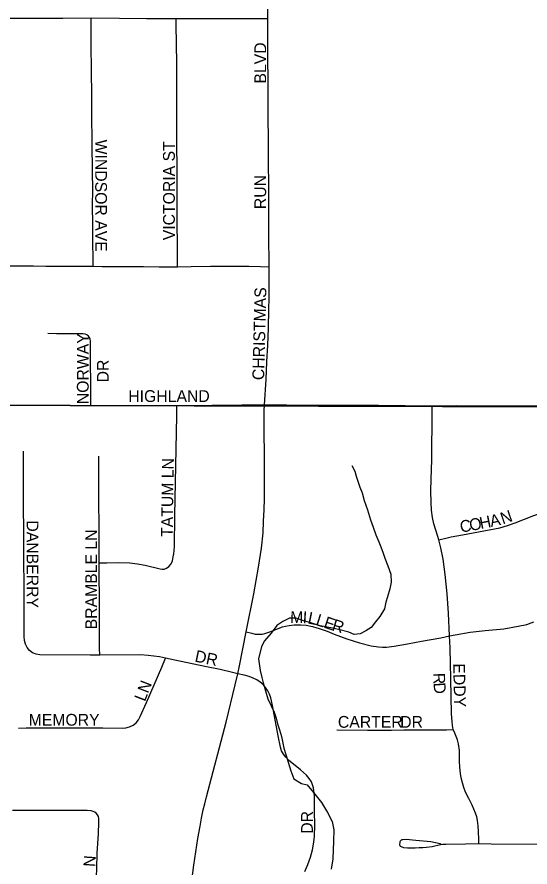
# Model space of a CAD drawing. Extents: x 1985906 to 2360102, y 891258 to 1222054.
# Drawn here: x 2121160 to 2123335, y 1028885 to 1032490 of the extents above; entities that cross this region are included whole.
import ezdxf

# ---------------------------------------------------------------- set-up
doc = ezdxf.new("R2010")
doc.units = 0
for name, color, linetype in [('GM_X_City_Street', 7, 'Continuous'), ('GM_X_City_Street_Text', 7, 'Continuous'), ('GM_X_Minor_River', 7, 'Continuous'), ('GM_X_Section', 7, 'Continuous')]:
    doc.layers.add(name, color=color, linetype=linetype)

msp = doc.modelspace()

# ---------------------------------------------------------------- linework, layer by layer
at = {"layer": 'GM_X_City_Street'}
for points in [[(2122223.4, 1032482.7), (2122223.8, 1032539.7), (2122224, 1032565.7), (2122224.2, 1032594.4), (2122224.7, 1032651.3)], [(2121115.7, 1032484.6), (2121222, 1032484.9), (2121299.3, 1032485.1), (2121354.8, 1032485.2), (2121474.6, 1032485.5)], [(2121474.6, 1032485.5), (2121595.4, 1032484.5), (2121710, 1032483.7), (2121824.3, 1032482.8), (2121835.6, 1032482.8)], [(2121483.5, 1031432.5), (2121483, 1031469.8), (2121482.2, 1031529.6), (2121481.8, 1031559.1), (2121481.4, 1031609.5), (2121481.2, 1031632.7), (2121481.1, 1031667.7), (2121481.1, 1031698.2), (2121481.6, 1031747.4), (2121479.3, 1031943.8), (2121478.1, 1032090.9), (2121476.9, 1032190.4), (2121476.4, 1032228.6), (2121475.6, 1032287.2), (2121475.1, 1032346.7), (2121474.6, 1032401.2), (2121474.6, 1032457.8), (2121474.6, 1032485.5)], [(2121835.6, 1032482.8), (2121978.3, 1032483.4), (2122069.6, 1032483.7), (2122152.8, 1032483.8), (2122184.1, 1032483.8), (2122223.4, 1032482.7)], [(2121840.3, 1031430.4), (2121840.2, 1031471.4), (2121839.9, 1031668.3), (2121839.4, 1031832.6), (2121838.4, 1031964), (2121837.3, 1032095.3), (2121837.5, 1032292.4), (2121835.8, 1032457.5), (2121835.6, 1032482.8)], [(2122228.9, 1031430.7), (2122228.8, 1031463), (2122228.6, 1031535.9), (2122228.5, 1031575), (2122228.5, 1031745.4), (2122227, 1031903.2), (2122226.6, 1031939.7), (2122226.2, 1031977), (2122225.4, 1032058.3), (2122224.8, 1032166.3), (2122224.6, 1032210.6), (2122223.9, 1032325.2), (2122223.4, 1032482.7)], [(2121110.2, 1031434.1), (2121133.3, 1031434.3), (2121166.7, 1031434.1), (2121230, 1031433.8), (2121282.1, 1031433.5), (2121369.8, 1031433.1), (2121483.5, 1031432.5)], [(2121483.5, 1031432.5), (2121521.8, 1031432.3), (2121569.5, 1031432), (2121627.7, 1031431.7), (2121696.3, 1031431.2), (2121763.2, 1031430.8), (2121840.3, 1031430.4)], [(2121840.3, 1031430.4), (2121898.9, 1031431.6), (2121980.5, 1031432.4), (2122094.7, 1031432.6), (2122143.5, 1031432.5), (2122192.2, 1031431.5), (2122228.9, 1031430.7)], [(2122209.7, 1030845.2), (2122216.7, 1030952.4), (2122220.2, 1031027.1), (2122223.6, 1031097.4), (2122226.3, 1031169.5), (2122228, 1031251.1), (2122228.9, 1031295.4), (2122229.8, 1031383.1), (2122228.9, 1031430.7)], [(2121473.9, 1030841.8), (2121473.7, 1030860.6), (2121473.4, 1030904.4), (2121473.2, 1030923.6), (2121472.9, 1030961.5), (2121472.6, 1030998.4), (2121472.4, 1031025.5), (2121472, 1031064.8), (2121471.7, 1031114.6), (2121470.1, 1031122.9), (2121468.7, 1031128.2), (2121466.5, 1031132.5), (2121463.5, 1031136.8), (2121456.1, 1031141.9), (2121449, 1031144.4), (2121440.1, 1031146), (2121393.1, 1031146.3), (2121363, 1031146.4), (2121327.1, 1031146.6), (2121290.7, 1031146.9)], [(2121093.7, 1030843.1), (2121181.9, 1030842.9), (2121473.9, 1030841.8)], [(2121473.9, 1030841.8), (2121542.9, 1030841.5), (2121838.2, 1030842.6)], [(2121509.3, 1030174.9), (2121540.7, 1030175.3), (2121589.7, 1030175.9), (2121638.7, 1030174.3), (2121671.2, 1030170.8), (2121703.4, 1030164.9), (2121766.9, 1030149.3), (2121775.3, 1030148.2), (2121784.8, 1030148.6), (2121793.9, 1030151.9), (2121804.6, 1030159.4), (2121813.5, 1030171.2), (2121819.5, 1030184.1), (2121822.8, 1030200.7), (2121825.1, 1030213.7), (2121826.6, 1030227.8), (2121827.7, 1030244), (2121830.1, 1030374.9), (2121837.5, 1030799.9), (2121838.2, 1030842.6)], [(2121838.2, 1030842.6), (2121986.1, 1030843.1), (2122018.7, 1030843.7)], [(2122018.7, 1030843.7), (2122113.1, 1030845.3), (2122209.7, 1030845.2)], [(2122132.1, 1029882.2), (2122164, 1030043.6), (2122184.8, 1030156.3), (2122196.7, 1030237.3), (2122203.3, 1030302.4), (2122205.9, 1030351.4), (2122208.5, 1030399.2), (2122209.1, 1030446.1), (2122209.6, 1030564.2), (2122209, 1030631.9), (2122208.2, 1030732.6), (2122208.8, 1030820.4), (2122209.7, 1030845.2)], [(2122209.7, 1030845.2), (2122303.4, 1030845.3), (2122482.3, 1030843.3), (2122692.5, 1030843.2), (2122920.7, 1030841.2)], [(2122948.6, 1030272.3), (2122945, 1030286.9), (2122927.2, 1030339.9), (2122921.4, 1030367), (2122917.3, 1030399), (2122916.3, 1030431.5), (2122914.8, 1030480.7), (2122916.5, 1030530.4), (2122918.7, 1030611.8), (2122918.6, 1030677.6), (2122920.5, 1030750), (2122920.5, 1030812.6), (2122920.7, 1030841.2)], [(2122920.7, 1030841.2), (2123021.8, 1030841.8), (2123250.6, 1030841.1), (2123413.4, 1030841), (2123599.9, 1030840.4), (2123847.1, 1030841)], [(2121510.9, 1029784.1), (2121470.6, 1029784.1), (2121257.6, 1029784.4), (2121241.5, 1029787), (2121226.4, 1029793.1), (2121213.3, 1029802.7), (2121202.9, 1029815.3), (2121195.7, 1029829.9), (2121191.7, 1029845.8), (2121190.2, 1029862.1), (2121190.5, 1030091.5), (2121189.2, 1030173.4), (2121189.4, 1030304.4), (2121187.8, 1030419.1), (2121188.2, 1030648.4)], [(2121509.3, 1030174.9), (2121509.1, 1030268.7), (2121507.9, 1030496.6), (2121507.3, 1030626.6)], [(2122948.6, 1030272.3), (2122984.7, 1030280.8), (2123000.7, 1030284.6), (2123049.1, 1030294), (2123162.3, 1030314.2), (2123207.1, 1030323.5), (2123239.8, 1030332.9), (2123273, 1030344.5), (2123351.3, 1030375.8), (2123419.2, 1030397.6), (2123515.9, 1030428.8), (2123570.5, 1030445.9), (2123611.9, 1030452.9), (2123669.6, 1030459.2), (2123723.4, 1030462.2), (2123774.9, 1030462.2), (2123831.8, 1030462.2), (2123859.4, 1030462.2)], [(2122994.3, 1029865), (2122990.3, 1029961.8), (2122984.5, 1030043.8), (2122976.2, 1030125.6), (2122966.6, 1030190.6), (2122956.9, 1030239), (2122948.6, 1030272.3)], [(2121510.9, 1029784.1), (2121510.8, 1029813.4), (2121509.8, 1029992.2), (2121509.3, 1030154.9), (2121509.3, 1030174.9)], [(2122132.1, 1029882.2), (2122155.3, 1029876.5), (2122170.3, 1029872.8), (2122179.4, 1029872), (2122186.6, 1029872), (2122200, 1029872.8), (2122211.5, 1029874.8), (2122235.9, 1029884.4), (2122267, 1029897), (2122286.2, 1029902.9), (2122298.4, 1029907), (2122314.6, 1029909.2), (2122335.8, 1029911.8), (2122363.9, 1029912.5), (2122386.1, 1029910.3), (2122412.7, 1029904.4), (2122441.6, 1029896.2), (2122474.9, 1029885.1), (2122504.5, 1029872.5), (2122559.2, 1029853.3), (2122611.8, 1029836.3), (2122661.2, 1029823.1), (2122693.6, 1029818.4), (2122710, 1029817.4), (2122726.3, 1029817.6), (2122758.9, 1029821.5), (2122815.2, 1029831), (2122875.2, 1029842.9), (2122957.3, 1029857.6), (2122994.3, 1029865)], [(2122994.3, 1029865), (2123017.3, 1029869.5), (2123081.6, 1029880.6), (2123145.3, 1029888.7), (2123223.7, 1029895.3), (2123285.1, 1029905.7), (2123322.1, 1029913.8), (2123339.9, 1029920.4), (2123351, 1029924.9)], [(2122096.1, 1029704.6), (2122103.6, 1029738.2), (2122132.1, 1029882.2)], [(2123009.9, 1029468.2), (2123008.2, 1029476.2), (2123006.4, 1029484.6), (2123005.4, 1029501.8), (2123002.7, 1029534.5), (2123000.1, 1029682.5), (2122996.1, 1029814), (2122994.3, 1029865)], [(2121166.4, 1029474.1), (2121199, 1029474.6), (2121361.7, 1029474.9), (2121524.4, 1029474.8), (2121605.8, 1029474.1), (2121622, 1029475.5), (2121637.8, 1029479.4), (2121652.5, 1029486.3), (2121665.3, 1029496.3), (2121675.4, 1029508.9), (2121683.2, 1029523.2), (2121708.8, 1029583), (2121773.7, 1029732.3), (2121790.4, 1029770.7)], [(2121790.4, 1029770.7), (2121764.9, 1029776.1), (2121716.2, 1029782.5), (2121683.5, 1029784.3), (2121510.9, 1029784.1)], [(2122096.1, 1029704.6), (2122073.7, 1029709.8), (2122021.2, 1029722), (2121957.1, 1029735.2), (2121829, 1029762.7), (2121790.4, 1029770.7)], [(2121880.6, 1028665.7), (2121884.4, 1028697.4), (2121909.6, 1028892.4), (2121926.6, 1029005.8), (2121936.4, 1029058.2), (2121942.5, 1029091.5), (2121950.3, 1029127.1), (2121956.4, 1029153.2), (2121963.9, 1029182.1), (2122046.5, 1029499.2), (2122085.8, 1029658.2), (2122096.1, 1029704.6)], [(2122380.4, 1028865.7), (2122393.9, 1028895.5), (2122404.9, 1028926.3), (2122413.1, 1028957.9), (2122418.2, 1028990.1), (2122421.2, 1029015.6), (2122423, 1029062.5), (2122422.2, 1029121.5), (2122421.8, 1029145), (2122421.3, 1029185.8), (2122417, 1029221.4), (2122412.6, 1029233.5), (2122408.3, 1029245.7), (2122398.7, 1029260.4), (2122387.1, 1029274.8), (2122362.3, 1029297.8), (2122310.7, 1029338.5), (2122299.8, 1029350.6), (2122290.1, 1029363.8), (2122282.3, 1029378.1), (2122277.3, 1029393.7), (2122267.9, 1029441.9), (2122243.8, 1029570.6), (2122236.1, 1029602.4), (2122230.7, 1029617.9), (2122223.5, 1029632.5), (2122214.4, 1029646.1), (2122203.5, 1029658.3), (2122191.2, 1029669.1), (2122177.8, 1029678.5), (2122161.5, 1029686.3), (2122145, 1029692.4), (2122123.1, 1029698.5), (2122096.1, 1029704.6)], [(2122517, 1029467.2), (2122645.7, 1029465.5), (2122747.5, 1029465.5), (2122800.1, 1029466.2), (2122834, 1029466.1), (2122899, 1029466.8), (2122941.2, 1029466.8), (2122981.1, 1029466.5), (2123009.9, 1029468.2)], [(2123118.4, 1028984.3), (2123118, 1029001.8), (2123116.5, 1029036.2), (2123114.8, 1029059.3), (2123112.5, 1029081.6), (2123109.3, 1029098.4), (2123104.5, 1029113.6), (2123090.1, 1029147.1), (2123076.6, 1029175.8), (2123062.2, 1029202.1), (2123054.3, 1029222.9), (2123048.7, 1029242), (2123043.9, 1029263.6), (2123040.7, 1029281.1), (2123037.5, 1029308.3), (2123036.7, 1029333.8), (2123035.9, 1029379.3), (2123032.8, 1029407.2), (2123028, 1029424), (2123022.4, 1029438.4), (2123016, 1029452.7), (2123009.9, 1029468.2)], [(2121492.6, 1028742.7), (2121498.5, 1028878.5), (2121500.6, 1028943.8), (2121505.2, 1029025.6), (2121507.4, 1029074.7), (2121507.2, 1029091.2), (2121505.3, 1029099.6), (2121501.7, 1029106.3), (2121496.5, 1029112.7), (2121490, 1029117.5), (2121483, 1029121.1), (2121474.9, 1029123.2), (2121458.5, 1029124.9), (2121141.7, 1029124.6)], [(2122958.2, 1028981.6), (2122954.3, 1028982.7), (2122915.3, 1028991.1), (2122851, 1028997.1), (2122810.8, 1029001.2), (2122796, 1029000.4), (2122791.5, 1028999.6), (2122789.1, 1028998.7), (2122786.6, 1028996.7), (2122785.2, 1028994.6), (2122783.9, 1028991.5), (2122782.8, 1028987.3), (2122782.4, 1028982.2), (2122782.5, 1028979.8), (2122783.3, 1028976.8), (2122785.5, 1028973.8), (2122788.4, 1028971.7), (2122799.3, 1028967.2), (2122815.9, 1028966.7), (2122848.8, 1028967), (2122865.2, 1028967.3), (2122881.2, 1028967.9), (2122896.7, 1028968.9), (2122920.4, 1028972.5), (2122955.1, 1028980.1), (2122965.3, 1028981.3), (2122978.4, 1028981.9), (2123062.1, 1028983.3), (2123118.4, 1028984.3)], [(2123118.4, 1028984.3), (2123170.9, 1028983.4), (2123378.5, 1028981.2)]]:
    msp.add_lwpolyline(points, dxfattribs=at)
at = {"layer": 'GM_X_Minor_River'}
msp.add_lwpolyline([(2122580, 1030587.7), (2122592.3, 1030563.7), (2122598.6, 1030541.8), (2122613.3, 1030495.8), (2122623.6, 1030471.9), (2122632.1, 1030439.9), (2122646.7, 1030400), (2122659.3, 1030358), (2122669.7, 1030326.1), (2122682.2, 1030294.2), (2122694.6, 1030264.2), (2122702.9, 1030242.3), (2122713.3, 1030216.4), (2122719.6, 1030194.4), (2122732.1, 1030162.5), (2122744.6, 1030126.5), (2122747, 1030092.5), (2122741.4, 1030064.3), (2122731.8, 1030030.1), (2122724, 1030007.9), (2122718.4, 1029979.8), (2122698.7, 1029947.4), (2122680.9, 1029925.1), (2122661.2, 1029900.8), (2122639.3, 1029886.4), (2122615.3, 1029874.1), (2122589.2, 1029871.7), (2122567, 1029881.5), (2122522.7, 1029892.9), (2122498.5, 1029898.6), (2122446.2, 1029907.9), (2122401.8, 1029921.4), (2122375.6, 1029929.1), (2122343.4, 1029940.7), (2122315.2, 1029940.3), (2122287.3, 1029925.9), (2122261.4, 1029909.5), (2122237.8, 1029877.1), (2122210.1, 1029844.6), (2122196.3, 1029820.4), (2122184.9, 1029768.1), (2122191.6, 1029718), (2122198, 1029688), (2122204.3, 1029666), (2122223.3, 1029598.1), (2122250.1, 1029542.3), (2122258.5, 1029516.3), (2122264.8, 1029492.3), (2122273.2, 1029466.4), (2122281.6, 1029438.4), (2122288, 1029410.4), (2122292.3, 1029388.4), (2122300.7, 1029362.5), (2122321.6, 1029292.5), (2122334.1, 1029258.6), (2122366.5, 1029239), (2122390.7, 1029233.3), (2122417.2, 1029201.5), (2122451.9, 1029157.9), (2122476.5, 1029116.1), (2122497.1, 1029078.3), (2122503.6, 1029042.2), (2122502.2, 1028994.1), (2122499.2, 1028919.8), (2122491.7, 1028875.6)], dxfattribs=at)
at = {"layer": 'GM_X_Section'}
for points in [[(2119771.9, 1036177.8), (2125019.2, 1036172.5), (2125066.6, 1030831.6), (2119807.2, 1030846.8)], [(2125066.6, 1030831.6), (2125102, 1025486.6), (2119810.6, 1025501.6), (2119807.2, 1030846.8)]]:
    msp.add_lwpolyline(points, close=True, dxfattribs=at)

# ---------------------------------------------------------------- texts
at = {"layer": 'GM_X_City_Street_Text'}
for s, rotation, p in [('BLVD', 90, (2122216.7, 1032207.3)), ('WINDSOR AVE', 270, (2121491.9, 1031969.7)), ('VICTORIA ST', 90, (2121829.5, 1031542.9)), ('RUN', 90, (2122216.7, 1031674.9)), ('CHRISTMAS', 88.566, (2122207.9, 1030949.2)), ('NORWAY', 90, (2121464.3, 1030847.7)), ('DR', 90, (2121549.4, 1030940.1)), ('HIGHLAND', 0, (2121632.1, 1030857.1)), ('TATUM LN', 89.1935, (2121820.7, 1030284.6)), ('A', 12.0709, (2123170.3, 1030326.6)), ('N', 19.1041, (2123219.8, 1030337.6)), ('DANBERRY', 270, (2121201.3, 1030354.9)), ('C', 9.2667, (2123042.2, 1030302.9)), ('O', 11.006, (2123083, 1030309.5)), ('H', 11.1342, (2123126.3, 1030318)), ('BRAMBLE LN', 90, (2121499.7, 1029892.9)), ('M', 359.6175, (2122318.4, 1029919.9)), ('I', 356.631, (2122370.5, 1029919.6)), ('L', 348.6418, (2122390.7, 1029918.5)), ('L', 342.3771, (2122423.8, 1029911.9)), ('E', 341.3663, (2122457.1, 1029901.3)), ('R', 343.398, (2122492.3, 1029889.5)), ('DR', 348.1183, (2121911.2, 1029756.7)), ('EDDY', 271.4681, (2123009.3, 1029747.9)), ('R', 271.6033, (2122924.9, 1029707.7)), ('LN', 68.7512, (2121702.6, 1029583.9)), ('D', 274.1003, (2122926.1, 1029665.8)), ('MEMORY', 0, (2121209.7, 1029484.3)), ('CARTER', 0, (2122520.9, 1029475.5)), ('DR', 0, (2122784.9, 1029475.5)), ('DR', 90, (2122414.7, 1029026.1)), ('N', 86.2819, (2121491.5, 1028884.4))]:
    msp.add_text(s, height=50, rotation=rotation, dxfattribs=at).set_placement(p)

doc.saveas('drawing.dxf')
